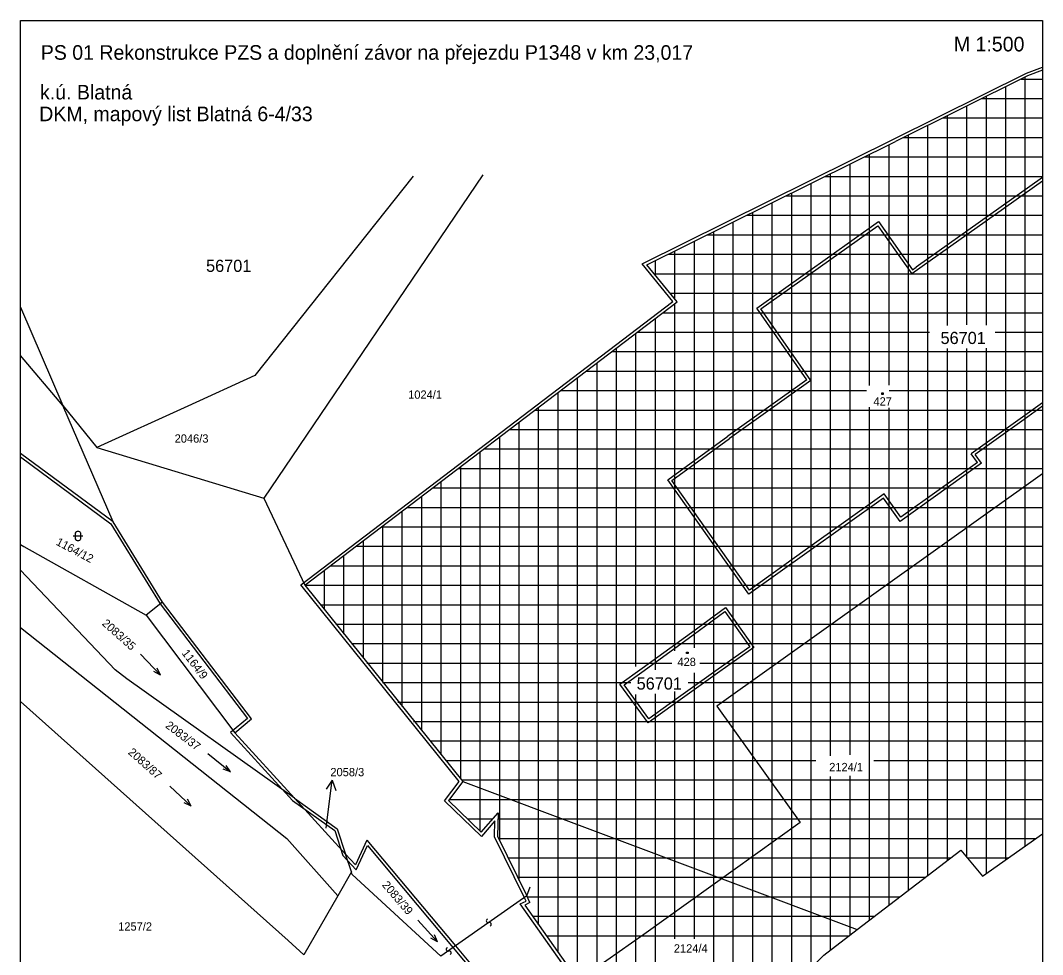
# Model space of a CAD drawing. Extents: x -792659 to -786947, y -1118170 to -1109641.
# Drawn here: x -792453.4 to -792348.4, y -1109945.1 to -1109849.1 of the extents above; entities that cross this region are included whole.
import ezdxf

# ---------------------------------------------------------------- set-up
doc = ezdxf.new("R2010")
doc.units = 0
doc.layers.add('1', color=7, linetype='Continuous')

# ---------------------------------------------------------------- blocks, each defined once
blk = doc.blocks.new('Z4022')
at = {"layer": '1'}
for p, q in [((-0.1, 0.1), (0.2, 0.1)), ((-0.1, -0.2), (-0.1, 0.1)), ((0.2, 0.1), (0.2, -0.2)), ((0.2, -0.2), (-0.1, -0.2))]:
    blk.add_line(p, q, dxfattribs=at)
blk = doc.blocks.new('Z42000')
at = {"layer": '1'}
blk.add_line((0, 0), (-0.7, -0.7), dxfattribs=at)
blk = doc.blocks.new('Z8021')
at = {"layer": '1'}
for p, q in [((-3, 0), (3, 0)), ((3, 0), (1.5, 0.5)), ((3, 0), (1.5, -0.5))]:
    blk.add_line(p, q, dxfattribs=at)
blk = doc.blocks.new('Z613')
at = {"layer": '1'}
for p, q in [((0, 3), (-0.5, 2)), ((0, 0), (0, 3)), ((0, 3), (0.5, 2))]:
    blk.add_line(p, q, dxfattribs=at)
blk = doc.blocks.new('Z31602')
at = {"layer": '1'}
for p, q in [((-1, 1), (1, 1)), ((-0.5, 1.6), (-0.4, 1.8)), ((-0.5, 0.4), (-0.5, 1.6)), ((-0.4, 0.2), (-0.5, 0.4)), ((-0.4, 1.8), (-0.3, 1.9)), ((-0.3, 0.1), (-0.4, 0.2)), ((-0.3, 1.9), (-0.1, 2)), ((-0.1, 0), (-0.3, 0.1)), ((-0.1, 2), (0.1, 2)), ((0.1, 0), (-0.1, 0)), ((0.1, 2), (0.3, 1.9)), ((0.3, 0.1), (0.1, 0)), ((0.3, 1.9), (0.4, 1.8)), ((0.4, 0.2), (0.3, 0.1)), ((0.4, 1.8), (0.5, 1.6)), ((0.5, 0.4), (0.4, 0.2)), ((0.5, 1.6), (0.5, 0.4))]:
    blk.add_line(p, q, dxfattribs=at)

msp = doc.modelspace()

# ---------------------------------------------------------------- linework, layer by layer
at = {"layer": '1'}
for p, q in [((-792349.96, -1109854.83), (-792363.55, -1109861.57)), ((-792350.62, -1109855.16), (-792348.43, -1109855.16)), ((-792350.2, -1109933.95), (-792350.2, -1109854.95)), ((-792348.43, -1109854.26), (-792349.96, -1109854.83)), ((-792352.2, -1109935.36), (-792352.2, -1109855.94)), ((-792354.66, -1109857.16), (-792348.43, -1109857.16)), ((-792354.2, -1109880.45), (-792354.2, -1109856.93)), ((-792356.2, -1109880.42), (-792356.2, -1109857.92)), ((-792358.69, -1109859.16), (-792348.43, -1109859.16)), ((-792358.2, -1109880.49), (-792358.2, -1109858.92)), ((-792360.2, -1109936.97), (-792360.2, -1109859.91)), ((-792362.72, -1109861.16), (-792348.43, -1109861.16)), ((-792362.2, -1109938.51), (-792362.2, -1109860.9)), ((-792389.09, -1109874.23), (-792363.55, -1109861.57)), ((-792364.2, -1109886.59), (-792364.2, -1109861.89)), ((-792366.76, -1109863.16), (-792348.43, -1109863.16)), ((-792366.2, -1109886.63), (-792366.2, -1109862.88)), ((-792368.2, -1109924.57), (-792368.2, -1109863.87)), ((-792413.08, -1109865.13), (-792429.34, -1109885.63)), ((-792405.94, -1109865), (-792428.41, -1109898.21)), ((-792370.79, -1109865.16), (-792348.43, -1109865.16)), ((-792370.2, -1109924.67), (-792370.2, -1109864.86)), ((-792348.43, -1109865.66), (-792361.87, -1109875.18)), ((-792348.43, -1109865.29), (-792361.41, -1109874.49)), ((-792372.2, -1109946.49), (-792372.2, -1109865.86)), ((-792376.2, -1109950.53), (-792376.2, -1109867.84)), ((-792374.83, -1109867.16), (-792348.43, -1109867.16)), ((-792374.2, -1109948.51), (-792374.2, -1109866.85)), ((-792378.2, -1109952.54), (-792378.2, -1109868.83)), ((-792380.2, -1109954.56), (-792380.2, -1109869.82)), ((-792378.86, -1109869.16), (-792348.43, -1109869.16)), ((-792377.79, -1109878.69), (-792365.28, -1109869.81)), ((-792365.28, -1109869.81), (-792361.79, -1109874.77)), ((-792382.2, -1109956.58), (-792382.2, -1109870.81)), ((-792377.37, -1109878.76), (-792365.35, -1109870.23)), ((-792365.35, -1109870.23), (-792361.87, -1109875.18)), ((-792384.2, -1109913.58), (-792384.2, -1109871.81)), ((-792382.9, -1109871.16), (-792348.43, -1109871.16)), ((-792386.2, -1109877.78), (-792386.2, -1109872.8)), ((-792388.2, -1109875.32), (-792388.2, -1109873.79)), ((-792386.93, -1109873.16), (-792348.43, -1109873.16)), ((-792385.97, -1109878.06), (-792389.09, -1109874.23)), ((-792388.33, -1109875.16), (-792348.43, -1109875.16)), ((-792361.79, -1109874.77), (-792361.41, -1109874.49)), ((-792386.7, -1109877.16), (-792348.43, -1109877.16)), ((-792424.2, -1109907.16), (-792385.97, -1109878.06)), ((-792386.2, -1109913.9), (-792386.2, -1109878.24)), ((-792453.43, -1109878.59), (-792449.06, -1109888.71)), ((-792387.42, -1109879.16), (-792348.43, -1109879.16)), ((-792372.64, -1109886.06), (-792377.79, -1109878.69)), ((-792372.22, -1109886.13), (-792377.37, -1109878.76)), ((-792388.2, -1109915.86), (-792388.2, -1109879.76)), ((-792390.2, -1109915.49), (-792390.2, -1109881.28)), ((-792390.04, -1109881.16), (-792360.03, -1109881.16)), ((-792353.31, -1109881.16), (-792348.43, -1109881.16)), ((-792449.06, -1109888.71), (-792453.43, -1109883.56)), ((-792392.67, -1109883.16), (-792348.43, -1109883.16)), ((-792392.2, -1109951.08), (-792392.2, -1109882.8)), ((-792358.2, -1109935.44), (-792358.2, -1109882.85)), ((-792356.2, -1109935.12), (-792356.2, -1109882.85)), ((-792354.2, -1109936.77), (-792354.2, -1109882.81)), ((-792394.2, -1109948.95), (-792394.2, -1109884.32)), ((-792429.34, -1109885.63), (-792436.24, -1109888.75)), ((-792395.3, -1109885.16), (-792348.43, -1109885.16)), ((-792396.2, -1109947.31), (-792396.2, -1109885.85)), ((-792372.64, -1109886.06), (-792380.76, -1109891.84)), ((-792372.22, -1109886.13), (-792380.59, -1109892.08)), ((-792398.2, -1109944.86), (-792398.2, -1109887.37)), ((-792397.93, -1109887.16), (-792366.51, -1109887.16)), ((-792364.2, -1109887.16), (-792348.43, -1109887.16)), ((-792449.06, -1109888.71), (-792445.59, -1109893)), ((-792443.92, -1109900.63), (-792449.06, -1109888.71)), ((-792436.24, -1109888.75), (-792445.59, -1109893)), ((-792348.43, -1109888.41), (-792350.49, -1109889.88)), ((-792348.43, -1109888.78), (-792350.32, -1109890.12)), ((-792400.55, -1109889.16), (-792348.43, -1109889.16)), ((-792400.2, -1109942.03), (-792400.2, -1109888.89)), ((-792366.2, -1109941.57), (-792366.2, -1109888.86)), ((-792364.2, -1109940.04), (-792364.2, -1109888.95)), ((-792350.49, -1109889.88), (-792355.76, -1109893.65)), ((-792402.2, -1109937.48), (-792402.2, -1109890.41)), ((-792350.32, -1109890.12), (-792355.34, -1109893.72)), ((-792404.2, -1109933.42), (-792404.2, -1109891.94)), ((-792403.18, -1109891.16), (-792348.43, -1109891.16)), ((-792386.94, -1109896.32), (-792380.76, -1109891.84)), ((-792445.59, -1109893), (-792428.41, -1109898.21)), ((-792386.52, -1109896.39), (-792380.58, -1109892.08)), ((-792443.92, -1109900.63), (-792453.43, -1109893.61)), ((-792406.2, -1109932.42), (-792406.2, -1109893.46)), ((-792405.81, -1109893.16), (-792348.43, -1109893.16)), ((-792355.11, -1109894.55), (-792355.76, -1109893.65)), ((-792354.69, -1109894.62), (-792355.34, -1109893.72)), ((-792408.2, -1109927.06), (-792408.2, -1109894.98)), ((-792354.69, -1109894.62), (-792363.05, -1109900.6)), ((-792355.11, -1109894.55), (-792362.98, -1109900.18)), ((-792408.44, -1109895.16), (-792348.43, -1109895.16)), ((-792348.43, -1109895.7), (-792381.88, -1109919.59)), ((-792411.06, -1109897.16), (-792348.43, -1109897.16)), ((-792410.2, -1109924.57), (-792410.2, -1109896.5)), ((-792378.6, -1109908.09), (-792386.94, -1109896.32)), ((-792378.53, -1109907.67), (-792386.52, -1109896.39)), ((-792428.41, -1109898.21), (-792424.2, -1109907.16)), ((-792412.2, -1109922.08), (-792412.2, -1109898.03)), ((-792364.7, -1109897.78), (-792372.8, -1109903.57)), ((-792364.77, -1109898.2), (-792372.63, -1109903.82)), ((-792363.05, -1109900.6), (-792364.77, -1109898.2)), ((-792362.98, -1109900.18), (-792364.7, -1109897.78)), ((-792413.69, -1109899.16), (-792348.43, -1109899.16)), ((-792414.2, -1109919.6), (-792414.2, -1109899.55)), ((-792438.83, -1109908.9), (-792443.92, -1109900.63)), ((-792416.32, -1109901.16), (-792348.43, -1109901.16)), ((-792416.2, -1109917.11), (-792416.2, -1109901.07)), ((-792453.43, -1109902.99), (-792453.09, -1109903.18)), ((-792453.09, -1109903.18), (-792440.51, -1109910.24)), ((-792418.95, -1109903.16), (-792348.43, -1109903.16)), ((-792418.2, -1109914.62), (-792418.2, -1109902.59)), ((-792420.2, -1109912.14), (-792420.2, -1109904.11)), ((-792372.63, -1109903.82), (-792378.6, -1109908.09)), ((-792372.8, -1109903.57), (-792378.53, -1109907.67)), ((-792443.7, -1109915.86), (-792453.43, -1109905.6)), ((-792422.2, -1109909.65), (-792422.2, -1109905.64)), ((-792421.57, -1109905.16), (-792348.43, -1109905.16)), ((-792424.2, -1109907.16), (-792407.99, -1109927.32)), ((-792424.2, -1109907.16), (-792348.43, -1109907.16)), ((-792438.83, -1109908.9), (-792440.51, -1109910.24)), ((-792429.71, -1109920.9), (-792438.83, -1109908.9)), ((-792422.61, -1109909.16), (-792348.43, -1109909.16)), ((-792384.51, -1109912), (-792380.99, -1109909.44)), ((-792380.99, -1109909.44), (-792378.09, -1109913.54)), ((-792440.51, -1109910.24), (-792431.42, -1109922.33)), ((-792384.33, -1109912.24), (-792381.06, -1109909.86)), ((-792381.06, -1109909.86), (-792378.51, -1109913.47)), ((-792453.43, -1109911.5), (-792426.08, -1109933.16)), ((-792421.02, -1109911.16), (-792348.43, -1109911.16)), ((-792389.55, -1109915.67), (-792384.51, -1109912)), ((-792389.37, -1109915.91), (-792384.33, -1109912.24)), ((-792419.43, -1109913.16), (-792348.43, -1109913.16)), ((-792378.51, -1109913.47), (-792381.74, -1109915.77)), ((-792378.09, -1109913.54), (-792381.57, -1109916.02)), ((-792442.51, -1109916.76), (-792443.7, -1109915.86)), ((-792417.83, -1109915.16), (-792386.53, -1109915.16)), ((-792391.84, -1109917.33), (-792389.55, -1109915.67)), ((-792391.42, -1109917.4), (-792389.37, -1109915.91)), ((-792381.74, -1109915.77), (-792386.79, -1109919.39)), ((-792381.57, -1109916.02), (-792386.62, -1109919.63)), ((-792383.65, -1109915.16), (-792348.43, -1109915.16)), ((-792425.28, -1109929.04), (-792442.51, -1109916.76)), ((-792416.24, -1109917.16), (-792390.73, -1109917.16)), ((-792384.83, -1109917.16), (-792348.43, -1109917.16)), ((-792384.2, -1109943.47), (-792384.2, -1109916.17)), ((-792388.96, -1109921.29), (-792391.84, -1109917.33)), ((-792388.89, -1109920.87), (-792391.42, -1109917.4)), ((-792386.2, -1109943.47), (-792386.2, -1109918.06)), ((-792440.58, -1109930.57), (-792453.43, -1109919.1)), ((-792414.65, -1109919.16), (-792348.43, -1109919.16)), ((-792390.2, -1109953.09), (-792390.2, -1109918.38)), ((-792388.2, -1109954.75), (-792388.2, -1109918.33)), ((-792386.62, -1109919.63), (-792388.96, -1109921.29)), ((-792386.79, -1109919.39), (-792388.89, -1109920.87)), ((-792381.88, -1109919.59), (-792373.33, -1109931.54)), ((-792431.42, -1109922.33), (-792429.71, -1109920.9)), ((-792413.06, -1109921.16), (-792348.43, -1109921.16)), ((-792431.42, -1109922.33), (-792425.28, -1109929.04)), ((-792411.33, -1109923.16), (-792348.43, -1109923.16)), ((-792409.73, -1109925.16), (-792371.71, -1109925.16)), ((-792365.76, -1109925.16), (-792348.43, -1109925.16)), ((-792407.99, -1109927.32), (-792409.46, -1109929.26)), ((-792408.12, -1109927.16), (-792348.43, -1109927.16)), ((-792407.99, -1109927.32), (-792367.46, -1109942.54)), ((-792370.2, -1109944.64), (-792370.2, -1109926.8)), ((-792368.2, -1109943.11), (-792368.2, -1109926.73)), ((-792425.28, -1109929.04), (-792420.03, -1109934.77)), ((-792425.28, -1109929.04), (-792420.88, -1109932.17)), ((-792409.46, -1109929.26), (-792406.09, -1109932.53)), ((-792409.38, -1109929.16), (-792348.43, -1109929.16)), ((-792425.94, -1109943.64), (-792440.58, -1109930.57)), ((-792422.01, -1109932.1), (-792421.77, -1109930.17)), ((-792406.09, -1109932.53), (-792404.35, -1109930.54)), ((-792404.35, -1109930.54), (-792404.43, -1109932.95)), ((-792407.5, -1109931.16), (-792404.89, -1109931.16)), ((-792404.37, -1109931.16), (-792348.43, -1109931.16)), ((-792373.33, -1109931.54), (-792389.4, -1109943.05)), ((-792420.88, -1109932.17), (-792420.03, -1109934.77)), ((-792404.43, -1109932.95), (-792401.42, -1109939.07)), ((-792426.08, -1109933.16), (-792420.84, -1109939.05)), ((-792417.84, -1109933.35), (-792419.01, -1109935.88)), ((-792417.84, -1109933.35), (-792408.74, -1109944.21)), ((-792404.33, -1109933.16), (-792349.08, -1109933.16)), ((-792419.43, -1109936.6), (-792420.03, -1109934.77)), ((-792420.03, -1109934.77), (-792419.01, -1109935.88)), ((-792403.34, -1109935.16), (-792357.84, -1109935.16)), ((-792356.17, -1109935.16), (-792351.91, -1109935.16)), ((-792419.43, -1109936.6), (-792420.84, -1109939.05)), ((-792419.34, -1109936.86), (-792419.43, -1109936.6)), ((-792410.26, -1109945.28), (-792419.34, -1109936.86)), ((-792402.36, -1109937.16), (-792360.45, -1109937.16)), ((-792420.84, -1109939.05), (-792424.33, -1109945.11)), ((-792401.42, -1109939.07), (-792408.74, -1109944.21)), ((-792401.09, -1109939.74), (-792401.42, -1109939.07)), ((-792401.38, -1109939.16), (-792363.05, -1109939.16)), ((-792396.41, -1109947.92), (-792402.08, -1109939.9)), ((-792401.09, -1109939.74), (-792401.63, -1109940.01)), ((-792401.63, -1109940.01), (-792396.36, -1109947.46)), ((-792400.82, -1109941.16), (-792365.66, -1109941.16)), ((-792389.4, -1109943.05), (-792401.43, -1109951.47)), ((-792399.4, -1109943.16), (-792368.27, -1109943.16)), ((-792424.33, -1109945.11), (-792425.94, -1109943.64)), ((-792408.74, -1109944.21), (-792410.26, -1109945.28)), ((-792408.74, -1109944.21), (-792405.73, -1109947.8))]:
    msp.add_line(p, q, dxfattribs=at)
msp.add_lwpolyline([(-792453.43, -1109849.14), (-792348.43, -1109849.14), (-792348.43, -1109997.64), (-792453.43, -1109997.64)], close=True, dxfattribs=at)
for points in [[(-792348.43, -1109984.31), (-792373.1, -1109966.21), (-792383.86, -1109958.31), (-792390.18, -1109953.67), (-792395.12, -1109948.42), (-792395.58, -1109947.93), (-792395.97, -1109947.51), (-792396.41, -1109947.92), (-792402.08, -1109939.9), (-792401.49, -1109939.6), (-792401.69, -1109939.2), (-792404.73, -1109933.02), (-792404.68, -1109931.37), (-792406.07, -1109932.97), (-792409.86, -1109929.29), (-792408.37, -1109927.32), (-792424.63, -1109907.11), (-792386.4, -1109878.01), (-792389.56, -1109874.13), (-792363.68, -1109861.3), (-792350.08, -1109854.55), (-792348.43, -1109853.94)], [(-792453.43, -1109893.98), (-792444.15, -1109900.84), (-792439.08, -1109909.07), (-792430.12, -1109920.85), (-792431.85, -1109922.3), (-792425.48, -1109929.27), (-792421.13, -1109932.36)], [(-792421.13, -1109932.36), (-792420.3, -1109934.93), (-792418.93, -1109936.41), (-792417.77, -1109933.91), (-792408.97, -1109944.4), (-792405.96, -1109947.99), (-792402.94, -1109951.92), (-792402.2, -1109952.66), (-792396.42, -1109958.53), (-792390.42, -1109964.35), (-792351.04, -1109997.64)], [(-792354.59, -1109937.05), (-792348.43, -1109932.7)], [(-792367.46, -1109942.54), (-792356.82, -1109934.38), (-792354.59, -1109937.05)], [(-792383.68, -1109958.07), (-792370.89, -1109945.17), (-792367.46, -1109942.54)]]:
    msp.add_lwpolyline(points, dxfattribs=at)
for centre, start, end in [((-792405.39, -1109941.64), 111.4312, 291.4312), ((-792405.25, -1109941.99), 291.4312, 111.4312), ((-792409.51, -1109944.56), 111.4312, 291.4312), ((-792409.37, -1109944.91), 291.4312, 111.4312)]:
    msp.add_arc(centre, 0.188, start, end, dxfattribs=at)

# ---------------------------------------------------------------- block references
at = {"layer": '1', "xscale": 0.5, "yscale": 0.5}
for name, p in [('Z4022', (-792364.9, -1109887.46)), ('Z31602', (-792447.51, -1109902.6)), ('Z4022', (-792384.95, -1109914.08))]:
    msp.add_blockref(name, p, dxfattribs=at)
at = {"layer": '1'}
for p, xscale, yscale, rotation in [((-792440.07, -1109915.32), 0.5, 0.5, -46.23800000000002), ((-792433.02, -1109925.39), 0.5, 0.5, -39.507700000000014), ((-792436.99, -1109928.82), 0.49999999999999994, 0.5000000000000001, -43.0655), ((-792411.58, -1109942.69), 0.5, 0.49999999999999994, -47.66460000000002)]:
    msp.add_blockref('Z8021', p, dxfattribs=dict(at, xscale=xscale, yscale=yscale, rotation=rotation))
for name, p, rotation in [('Z613', (-792421.77, -1109930.17), -7.081900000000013), ('Z42000', (-792401.42, -1109939.07), -155.64700000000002)]:
    msp.add_blockref(name, p, dxfattribs=dict(at, rotation=rotation))

# ---------------------------------------------------------------- texts
for s, height, p in [('M 1:500', 1.5, (-792357.54, -1109852.32)), ('PS 01 Rekonstrukce PZS a doplnění závor na přejezdu P1348 v km 23,017', 1.5, (-792451.34, -1109853.18)), ('k.ú. Blatná', 1.5, (-792451.42, -1109857.26)), ('DKM, mapový list Blatná 6-4/33', 1.5, (-792451.5, -1109859.49)), ('56701', 1.25, (-792434.36, -1109874.97)), ('56701', 1.25, (-792358.91, -1109882.38)), ('1024/1', 0.85, (-792413.6, -1109888)), ('427', 0.85, (-792365.8, -1109888.7)), ('2046/3', 0.85, (-792437.59, -1109892.51)), ('428', 0.85, (-792385.94, -1109915.46)), ('56701', 1.25, (-792390.13, -1109917.88)), ('2124/1', 0.85, (-792370.35, -1109926.26)), ('2058/3', 0.85, (-792421.59, -1109926.78)), ('1257/2', 0.85, (-792443.39, -1109942.64)), ('2124/4', 0.85, (-792386.31, -1109944.89))]:
    msp.add_text(s, height=height, dxfattribs=at).set_placement(p)
for s, rotation, p in [('1164/12', 332.1027, (-792449.85, -1109902.97)), ('2083/35', 318.2637, (-792445.12, -1109911.18)), ('1164/9', 307.5555, (-792436.9, -1109914.15)), ('2083/37', 322.6929, (-792438.61, -1109921.71)), ('2083/87', 318.2666, (-792442.44, -1109924.42)), ('2083/39', 310.5251, (-792416.34, -1109937.98))]:
    msp.add_text(s, height=0.85, rotation=rotation, dxfattribs=at).set_placement(p)

doc.saveas('drawing.dxf')
